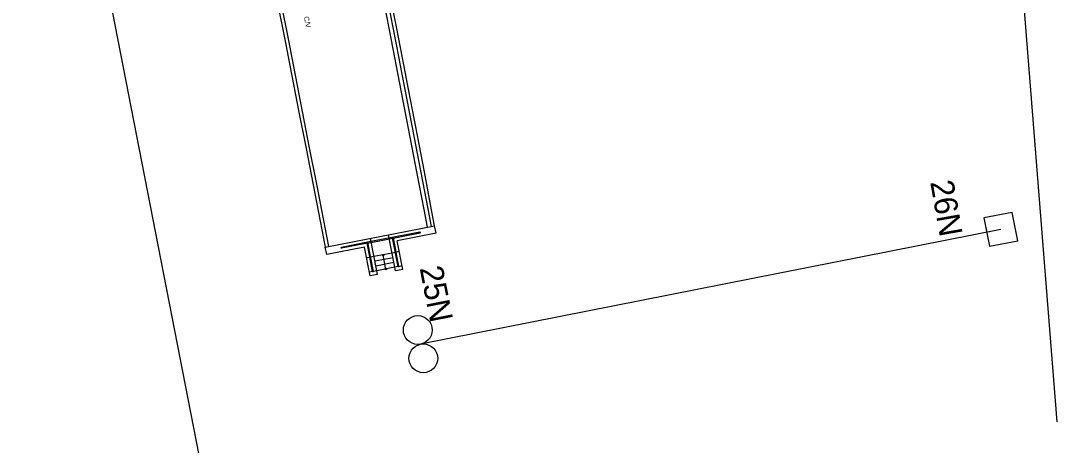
# Model space of a CAD drawing. Extents: x -545258 to -544992, y -1122311 to -1121664.
# Drawn here: x -545158.8 to -545102.8, y -1122251.8 to -1122228.8 of the extents above; entities that cross this region are included whole.
import ezdxf

# ---------------------------------------------------------------- set-up
doc = ezdxf.new("R2010")
doc.units = 0
for name, color, linetype in [('SO 18-01-01_3', 7, 'Continuous'), ('SO 18-01-01_4', 7, 'Continuous'), ('SO18-15-08', 7, 'Continuous'), ('SO18-16-02', 7, 'Continuous'), ('Vrstva 10', 7, 'Continuous')]:
    doc.layers.add(name, color=color, linetype=linetype)

msp = doc.modelspace()

# ---------------------------------------------------------------- linework, layer by layer
at = {"layer": 'SO 18-01-01_3'}
msp.add_line((-545105.838, -1122240.086), (-545137.195, -1122246.29), dxfattribs=at)
msp.add_lwpolyline([(-545104.923, -1122240.703), (-545105.222, -1122239.172), (-545106.753, -1122239.47), (-545106.455, -1122241.001)], close=True, dxfattribs=at)
for centre in [(-545137.345, -1122245.525), (-545137.046, -1122247.056)]:
    msp.add_circle(centre, 0.78, dxfattribs=at)
at = {"layer": 'SO 18-01-01_4'}
msp.add_lwpolyline([(-545102.793, -1122250.491), (-545106.116, -1122208.618), (-545109.928, -1122137.596), (-545106.412, -1122088.188), (-545106.367, -1122023.596), (-545108.703, -1121978.559), (-545127.424, -1121916.593), (-545139.015, -1121857.213), (-545147.82, -1121812.064), (-545159.299, -1121753.172), (-545170.035, -1121688.35), (-545174.127, -1121676.058)], dxfattribs=at)
at = {"layer": 'SO18-16-02'}
for p, q in [((-545142.344, -1122241.05), (-545136.434, -1122239.898)), ((-545137.231, -1122240.232), (-545140.065, -1122240.784)), ((-545140.056, -1122240.834), (-545137.221, -1122240.281)), ((-545136.36, -1122240.291), (-545138.452, -1122240.699)), ((-545140.065, -1122240.784), (-545141.469, -1122241.058)), ((-545140.056, -1122240.834), (-545141.461, -1122241.107)), ((-545140.219, -1122241.044), (-545142.267, -1122241.443)), ((-545139.711, -1122241.556), (-545139.883, -1122241.589)), ((-545138.73, -1122241.365), (-545139.711, -1122241.556)), ((-545139.22, -1122241.46), (-545139.263, -1122241.506)), ((-545139.164, -1122241.486), (-545139.263, -1122241.506)), ((-545139.22, -1122241.46), (-545139.164, -1122241.486)), ((-545138.558, -1122241.331), (-545138.73, -1122241.365)), ((-545138.337, -1122241.288), (-545138.509, -1122241.322)), ((-545139.932, -1122241.599), (-545140.104, -1122241.633)), ((-545138.68, -1122241.62), (-545139.661, -1122241.811)), ((-545138.63, -1122241.875), (-545139.612, -1122242.066)), ((-545138.58, -1122242.13), (-545139.562, -1122242.322)), ((-545138.409, -1122242.097), (-545138.58, -1122242.13)), ((-545138.188, -1122242.054), (-545138.36, -1122242.087)), ((-545139.783, -1122242.365), (-545139.955, -1122242.398)), ((-545139.524, -1122242.518), (-545139.916, -1122242.594)), ((-545139.562, -1122242.322), (-545139.734, -1122242.355)), ((-545138.149, -1122242.25), (-545138.542, -1122242.327))]:
    msp.add_line(p, q, dxfattribs=at)
for points in [[(-545136.827, -1122239.972), (-545137.006, -1122239.02), (-545137.379, -1122237.058), (-545137.754, -1122235.096), (-545138.132, -1122233.135), (-545138.512, -1122231.174), (-545138.569, -1122230.882), (-545138.895, -1122229.212), (-545139.278, -1122227.249)], [(-545136.611, -1122239.932), (-545136.79, -1122238.979), (-545137.163, -1122237.017), (-545137.538, -1122235.055), (-545137.916, -1122233.093), (-545138.296, -1122231.132), (-545138.353, -1122230.84), (-545138.679, -1122229.17), (-545139.062, -1122227.207)], [(-545136.434, -1122239.898), (-545136.613, -1122238.946), (-545136.986, -1122236.983), (-545137.361, -1122235.021), (-545137.739, -1122233.059), (-545138.12, -1122231.098), (-545138.177, -1122230.806), (-545138.502, -1122229.135), (-545138.885, -1122227.172)], [(-545144.916, -1122227.864), (-545144.533, -1122229.827), (-545144.15, -1122231.79), (-545143.767, -1122233.753), (-545143.384, -1122235.716), (-545143.001, -1122237.679), (-545142.619, -1122239.642), (-545142.344, -1122241.05)], [(-545144.739, -1122227.829), (-545144.356, -1122229.792), (-545143.974, -1122231.755), (-545143.591, -1122233.718), (-545143.208, -1122235.681), (-545142.825, -1122237.644), (-545142.442, -1122239.607), (-545142.167, -1122241.016)], [(-545138.58, -1122242.13), (-545138.921, -1122240.383)], [(-545136.36, -1122240.291), (-545136.434, -1122239.898)], [(-545139.783, -1122242.365), (-545140.085, -1122240.814)], [(-545139.734, -1122242.355), (-545140.036, -1122240.804)], [(-545139.562, -1122242.322), (-545139.902, -1122240.574)], [(-545138.409, -1122242.097), (-545138.711, -1122240.546)], [(-545138.36, -1122242.087), (-545138.662, -1122240.536)], [(-545138.149, -1122242.25), (-545138.452, -1122240.699)], [(-545142.267, -1122241.443), (-545142.344, -1122241.05)], [(-545139.916, -1122242.594), (-545140.219, -1122241.044)], [(-545139.064, -1122242.265), (-545139.22, -1122241.46)], [(-545138.542, -1122242.327), (-545138.58, -1122242.13)], [(-545139.524, -1122242.518), (-545139.562, -1122242.322)]]:
    msp.add_lwpolyline(points, dxfattribs=at)
for centre, radius in [((-545137.226, -1122240.256), 0.025), ((-545140.06, -1122240.809), 0.025), ((-545138.686, -1122240.541), 0.025), ((-545141.465, -1122241.083), 0.025), ((-545138.384, -1122242.092), 0.025), ((-545139.758, -1122242.36), 0.025), ((-545139.071, -1122242.226), 0.0396)]:
    msp.add_circle(centre, radius, dxfattribs=at)
at = {"layer": 'Vrstva 10'}
msp.add_line((-545258.291, -1121692.439), (-545137.778, -1122310.805), dxfattribs=at)

# ---------------------------------------------------------------- texts
at = {"layer": 'SO 18-01-01_3'}
for s, rotation, p in [('26N', 280.027, (-545109.66, -1122237.53)), ('25N', 281.0687, (-545137.247, -1122242.181))]:
    msp.add_text(s, height=1.25, rotation=rotation, dxfattribs=at).set_placement(p)
at = {"layer": 'SO18-15-08'}
msp.add_text('C/V', height=0.2688, rotation=281.121, dxfattribs=at).set_placement((-545143.504, -1122228.602))

doc.saveas('drawing.dxf')
